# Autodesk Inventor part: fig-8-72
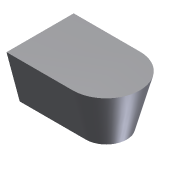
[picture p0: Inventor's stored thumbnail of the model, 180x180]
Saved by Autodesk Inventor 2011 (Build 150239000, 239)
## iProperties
Shininess: 77.0
Length Units: 11269
Angle Units: 11279
Time Units: 11290
Mass Units: 11283
Length Display Precision: 3
Angle Display Precision: 2
Created: 2002-01
Part Number: fig-8-72
Document SubType Name: Modeling
Designer: ***
Density: 1 g/cm^3
Density: 0.0
Volumn: 0.0
Area: 0.0
PropertySet Name: Model Information
Control State: 0
Master: False
Checked Out: False
Author: ***
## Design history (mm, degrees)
sketch "Sketch2"
  geometry: L1 (-19.86, 19.946)-(-19.86, -14.161); L2 (-19.86, -14.161)-(13.729, -14.161); L3 (13.729, 19.946)-(-19.86, 19.946); A1 r 17.054 centre (13.729, 2.893) between (13.729, -14.161) and (13.729, 19.946)
  constraints: 6 end point, 2 point on circle, 2 tangent, 1 centre point, 1 parallel, 1 perpendicular, 1 vertical
extrude "Extrusion2" new body sketch "Sketch2" distance "d6" = 25; taper "d7" = 0 deg
feature "FaceDraft8" dims angle "d14" = -15 deg
body "Solid1"
